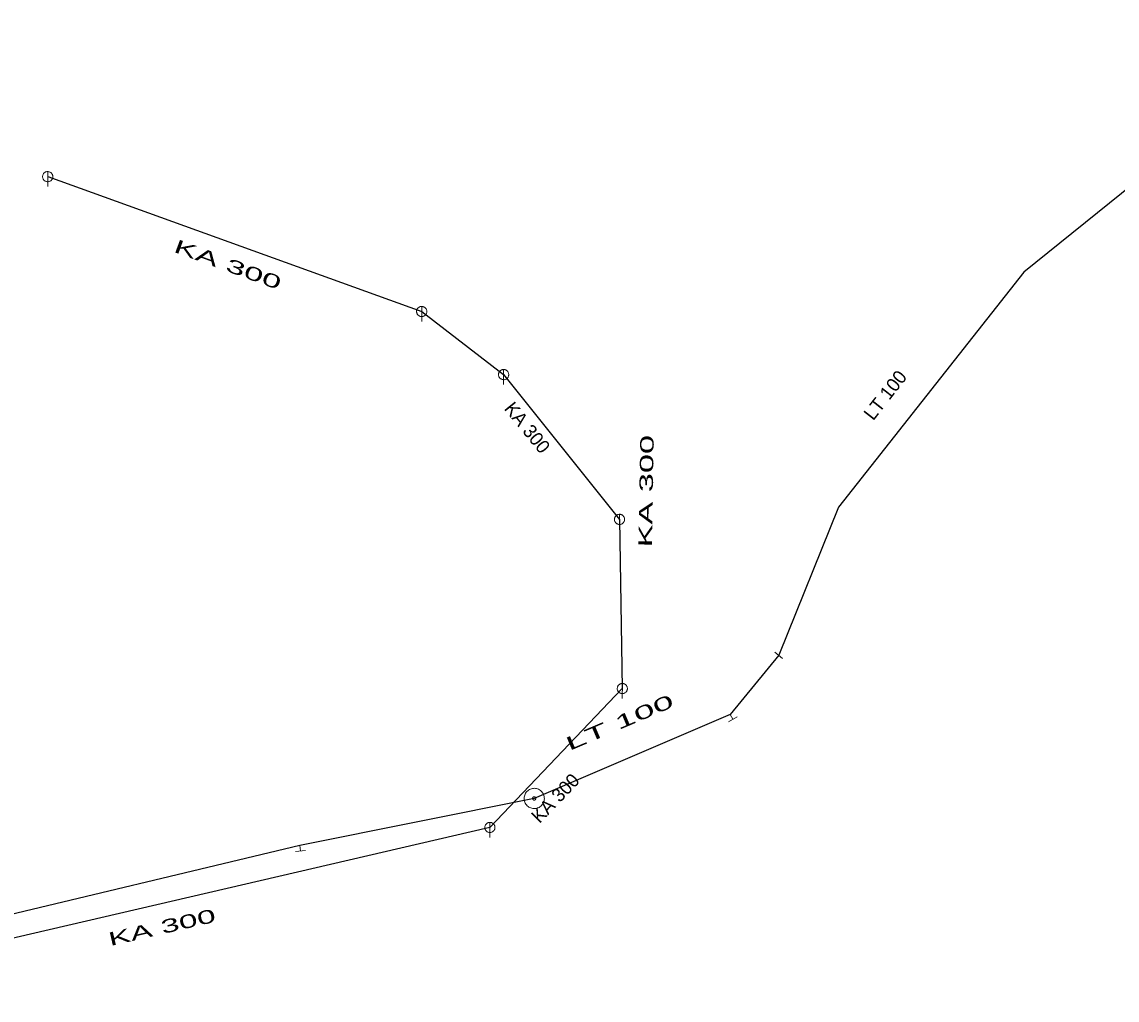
# Model space of a CAD drawing. Extents: x -687515 to -686506, y -974029 to -973461.
# Drawn here: x -687015 to -686960.9, y -973763.4 to -973715 of the extents above; entities that cross this region are included whole.
import ezdxf
from ezdxf.enums import TextEntityAlignment as Align

# ---------------------------------------------------------------- set-up
doc = ezdxf.new("R2010")
doc.units = 0
doc.header["$LTSCALE"] = 0.27
for name, color, linetype, lineweight in [('1', 7, 'Continuous', 13), ('14', 7, 'Continuous', 25), ('17', 7, 'Continuous', 25), ('22', 7, 'Continuous', 13), ('34', 7, 'Continuous', 13), ('47', 7, 'Continuous', 13)]:
    doc.layers.add(name, color=color, linetype=linetype, lineweight=lineweight)

msp = doc.modelspace()

# ---------------------------------------------------------------- linework, layer by layer
at = {"layer": '14'}
for p, q in [((-687013.763, -973722.649), (-686995.27, -973729.32)), ((-686995.27, -973729.32), (-686991.219, -973732.44)), ((-686985.35, -973747.969), (-686991.899, -973754.84)), ((-686991.899, -973754.84), (-687024.84, -973762.48))]:
    msp.add_line(p, q, dxfattribs=at)
at = {"layer": '14', "lineweight": 13}
for p, q in [((-686980.017, -973749.259), (-686979.889, -973749.489)), ((-687001.294, -973755.738), (-687001.27, -973756))]:
    msp.add_line(p, q, dxfattribs=at)
at = {"layer": '14'}
msp.add_lwpolyline([(-686991.219, -973732.44), (-686985.489, -973739.6), (-686985.35, -973747.969)], dxfattribs=at)
at = {"layer": '17'}
for points in [[(-686948.922, -973714.994), (-686954.652, -973718.63), (-686965.5, -973727.379), (-686974.664, -973738.999), (-686977.613, -973746.323)], [(-686977.613, -973746.323), (-686980.017, -973749.259), (-686989.707, -973753.404)], [(-686989.707, -973753.404), (-687001.294, -973755.738), (-687033.846, -973763.506), (-687042.734, -973766.009), (-687045.081, -973767.522), (-687056.296, -973773.572), (-687070.532, -973788), (-687086.733, -973803.447)]]:
    msp.add_lwpolyline(points, dxfattribs=at)
at = {"layer": '22'}
for p, q in [((-687013.762, -973722.397), (-687013.763, -973723.141)), ((-686995.269, -973729.068), (-686995.27, -973729.811)), ((-686991.218, -973732.188), (-686991.219, -973732.931)), ((-686985.488, -973739.348), (-686985.489, -973740.092)), ((-686985.349, -973747.717), (-686985.35, -973748.461)), ((-686991.898, -973754.588), (-686991.899, -973755.331))]:
    msp.add_line(p, q, dxfattribs=at)
for points in [[(-687013.511, -973722.649), (-687013.512, -973722.623), (-687013.516, -973722.597), (-687013.522, -973722.571), (-687013.532, -973722.547), (-687013.544, -973722.523), (-687013.558, -973722.501), (-687013.575, -973722.48), (-687013.593, -973722.462), (-687013.614, -973722.445), (-687013.636, -973722.431), (-687013.66, -973722.419), (-687013.684, -973722.409), (-687013.71, -973722.403), (-687013.736, -973722.399), (-687013.762, -973722.397), (-687013.788, -973722.398), (-687013.814, -973722.402), (-687013.84, -973722.408), (-687013.865, -973722.418), (-687013.888, -973722.43), (-687013.91, -973722.444), (-687013.931, -973722.461), (-687013.949, -973722.479), (-687013.966, -973722.5), (-687013.98, -973722.522), (-687013.992, -973722.546), (-687014.002, -973722.57), (-687014.009, -973722.596), (-687014.013, -973722.622), (-687014.015, -973722.648), (-687014.014, -973722.674), (-687014.01, -973722.7), (-687014.003, -973722.726), (-687013.993, -973722.751), (-687013.981, -973722.774), (-687013.967, -973722.796), (-687013.95, -973722.817), (-687013.932, -973722.835), (-687013.911, -973722.852), (-687013.889, -973722.866), (-687013.866, -973722.878), (-687013.841, -973722.888), (-687013.815, -973722.895), (-687013.789, -973722.899), (-687013.763, -973722.901), (-687013.737, -973722.9), (-687013.711, -973722.896), (-687013.685, -973722.889), (-687013.661, -973722.879), (-687013.637, -973722.867), (-687013.615, -973722.853), (-687013.594, -973722.836), (-687013.576, -973722.818), (-687013.559, -973722.797), (-687013.545, -973722.775), (-687013.533, -973722.752), (-687013.523, -973722.727), (-687013.517, -973722.701), (-687013.513, -973722.675)], [(-686995.018, -973729.32), (-686995.019, -973729.294), (-686995.023, -973729.268), (-686995.029, -973729.242), (-686995.039, -973729.218), (-686995.051, -973729.194), (-686995.065, -973729.172), (-686995.082, -973729.151), (-686995.1, -973729.133), (-686995.121, -973729.116), (-686995.143, -973729.102), (-686995.167, -973729.09), (-686995.191, -973729.08), (-686995.217, -973729.074), (-686995.243, -973729.07), (-686995.269, -973729.068), (-686995.295, -973729.069), (-686995.321, -973729.073), (-686995.347, -973729.079), (-686995.372, -973729.089), (-686995.395, -973729.101), (-686995.417, -973729.115), (-686995.438, -973729.132), (-686995.456, -973729.15), (-686995.473, -973729.171), (-686995.487, -973729.193), (-686995.499, -973729.217), (-686995.509, -973729.241), (-686995.516, -973729.267), (-686995.52, -973729.293), (-686995.522, -973729.319), (-686995.521, -973729.345), (-686995.517, -973729.371), (-686995.51, -973729.397), (-686995.5, -973729.422), (-686995.488, -973729.445), (-686995.474, -973729.467), (-686995.457, -973729.488), (-686995.439, -973729.506), (-686995.418, -973729.523), (-686995.396, -973729.537), (-686995.373, -973729.549), (-686995.348, -973729.559), (-686995.322, -973729.566), (-686995.296, -973729.57), (-686995.27, -973729.571), (-686995.244, -973729.571), (-686995.218, -973729.567), (-686995.192, -973729.56), (-686995.168, -973729.55), (-686995.144, -973729.538), (-686995.122, -973729.524), (-686995.101, -973729.507), (-686995.083, -973729.489), (-686995.066, -973729.468), (-686995.052, -973729.446), (-686995.04, -973729.423), (-686995.03, -973729.398), (-686995.024, -973729.372), (-686995.02, -973729.346)], [(-686990.967, -973732.44), (-686990.968, -973732.414), (-686990.972, -973732.388), (-686990.978, -973732.362), (-686990.988, -973732.338), (-686991, -973732.314), (-686991.014, -973732.292), (-686991.031, -973732.271), (-686991.049, -973732.253), (-686991.07, -973732.236), (-686991.092, -973732.222), (-686991.116, -973732.21), (-686991.14, -973732.2), (-686991.166, -973732.194), (-686991.192, -973732.19), (-686991.218, -973732.188), (-686991.244, -973732.189), (-686991.27, -973732.193), (-686991.296, -973732.199), (-686991.321, -973732.209), (-686991.344, -973732.221), (-686991.366, -973732.235), (-686991.387, -973732.252), (-686991.405, -973732.27), (-686991.422, -973732.291), (-686991.436, -973732.313), (-686991.448, -973732.337), (-686991.458, -973732.361), (-686991.465, -973732.387), (-686991.469, -973732.413), (-686991.471, -973732.439), (-686991.47, -973732.465), (-686991.466, -973732.491), (-686991.459, -973732.517), (-686991.449, -973732.542), (-686991.437, -973732.565), (-686991.423, -973732.587), (-686991.406, -973732.608), (-686991.388, -973732.626), (-686991.367, -973732.643), (-686991.345, -973732.657), (-686991.322, -973732.669), (-686991.297, -973732.679), (-686991.271, -973732.686), (-686991.245, -973732.69), (-686991.219, -973732.691), (-686991.193, -973732.691), (-686991.167, -973732.687), (-686991.141, -973732.68), (-686991.117, -973732.67), (-686991.093, -973732.658), (-686991.071, -973732.644), (-686991.05, -973732.627), (-686991.032, -973732.609), (-686991.015, -973732.588), (-686991.001, -973732.566), (-686990.989, -973732.543), (-686990.979, -973732.518), (-686990.973, -973732.492), (-686990.969, -973732.466)], [(-686985.237, -973739.6), (-686985.238, -973739.574), (-686985.242, -973739.548), (-686985.248, -973739.522), (-686985.258, -973739.498), (-686985.27, -973739.474), (-686985.284, -973739.452), (-686985.301, -973739.431), (-686985.319, -973739.413), (-686985.34, -973739.396), (-686985.362, -973739.382), (-686985.386, -973739.37), (-686985.41, -973739.36), (-686985.436, -973739.354), (-686985.462, -973739.35), (-686985.488, -973739.348), (-686985.514, -973739.349), (-686985.54, -973739.353), (-686985.566, -973739.359), (-686985.591, -973739.369), (-686985.614, -973739.381), (-686985.636, -973739.395), (-686985.657, -973739.412), (-686985.675, -973739.43), (-686985.692, -973739.451), (-686985.706, -973739.473), (-686985.718, -973739.497), (-686985.728, -973739.521), (-686985.735, -973739.547), (-686985.739, -973739.573), (-686985.74, -973739.599), (-686985.74, -973739.625), (-686985.736, -973739.651), (-686985.729, -973739.677), (-686985.719, -973739.702), (-686985.707, -973739.725), (-686985.693, -973739.747), (-686985.676, -973739.768), (-686985.658, -973739.786), (-686985.637, -973739.803), (-686985.615, -973739.817), (-686985.592, -973739.829), (-686985.567, -973739.839), (-686985.541, -973739.846), (-686985.515, -973739.85), (-686985.489, -973739.852), (-686985.463, -973739.851), (-686985.437, -973739.847), (-686985.411, -973739.84), (-686985.387, -973739.83), (-686985.363, -973739.818), (-686985.341, -973739.804), (-686985.32, -973739.787), (-686985.302, -973739.769), (-686985.285, -973739.748), (-686985.271, -973739.726), (-686985.259, -973739.703), (-686985.249, -973739.678), (-686985.243, -973739.652), (-686985.239, -973739.626)], [(-686985.098, -973747.969), (-686985.099, -973747.943), (-686985.103, -973747.917), (-686985.109, -973747.891), (-686985.119, -973747.867), (-686985.131, -973747.843), (-686985.145, -973747.821), (-686985.162, -973747.8), (-686985.18, -973747.782), (-686985.201, -973747.765), (-686985.223, -973747.751), (-686985.247, -973747.739), (-686985.271, -973747.729), (-686985.297, -973747.723), (-686985.323, -973747.719), (-686985.349, -973747.717), (-686985.375, -973747.718), (-686985.401, -973747.722), (-686985.427, -973747.728), (-686985.452, -973747.738), (-686985.475, -973747.75), (-686985.497, -973747.764), (-686985.518, -973747.781), (-686985.536, -973747.799), (-686985.553, -973747.82), (-686985.567, -973747.842), (-686985.579, -973747.866), (-686985.589, -973747.89), (-686985.596, -973747.916), (-686985.6, -973747.942), (-686985.602, -973747.968), (-686985.601, -973747.994), (-686985.597, -973748.02), (-686985.59, -973748.046), (-686985.58, -973748.071), (-686985.568, -973748.094), (-686985.554, -973748.116), (-686985.537, -973748.137), (-686985.519, -973748.155), (-686985.498, -973748.172), (-686985.476, -973748.186), (-686985.453, -973748.198), (-686985.428, -973748.208), (-686985.402, -973748.215), (-686985.376, -973748.219), (-686985.35, -973748.221), (-686985.324, -973748.22), (-686985.298, -973748.216), (-686985.272, -973748.209), (-686985.248, -973748.199), (-686985.224, -973748.187), (-686985.202, -973748.173), (-686985.181, -973748.156), (-686985.163, -973748.138), (-686985.146, -973748.117), (-686985.132, -973748.095), (-686985.12, -973748.072), (-686985.11, -973748.047), (-686985.104, -973748.021), (-686985.1, -973747.995)], [(-686991.647, -973754.84), (-686991.648, -973754.814), (-686991.652, -973754.788), (-686991.658, -973754.762), (-686991.668, -973754.738), (-686991.68, -973754.714), (-686991.694, -973754.692), (-686991.711, -973754.671), (-686991.729, -973754.653), (-686991.75, -973754.636), (-686991.772, -973754.622), (-686991.796, -973754.61), (-686991.82, -973754.6), (-686991.846, -973754.594), (-686991.872, -973754.59), (-686991.898, -973754.588), (-686991.924, -973754.589), (-686991.95, -973754.593), (-686991.976, -973754.599), (-686992.001, -973754.609), (-686992.024, -973754.621), (-686992.046, -973754.635), (-686992.067, -973754.652), (-686992.085, -973754.67), (-686992.102, -973754.691), (-686992.116, -973754.713), (-686992.128, -973754.737), (-686992.138, -973754.761), (-686992.145, -973754.787), (-686992.149, -973754.813), (-686992.151, -973754.839), (-686992.15, -973754.865), (-686992.146, -973754.891), (-686992.139, -973754.917), (-686992.129, -973754.942), (-686992.117, -973754.965), (-686992.103, -973754.987), (-686992.086, -973755.008), (-686992.068, -973755.026), (-686992.047, -973755.043), (-686992.025, -973755.057), (-686992.002, -973755.069), (-686991.977, -973755.079), (-686991.951, -973755.086), (-686991.925, -973755.09), (-686991.899, -973755.092), (-686991.873, -973755.091), (-686991.847, -973755.087), (-686991.821, -973755.08), (-686991.797, -973755.07), (-686991.773, -973755.058), (-686991.751, -973755.044), (-686991.73, -973755.027), (-686991.712, -973755.009), (-686991.695, -973754.988), (-686991.681, -973754.966), (-686991.669, -973754.943), (-686991.659, -973754.918), (-686991.653, -973754.892), (-686991.649, -973754.866)]]:
    msp.add_lwpolyline(points, close=True, dxfattribs=at)
at = {"layer": '34'}
for p, q in [((-686977.424, -973746.483), (-686977.801, -973746.162)), ((-686980.106, -973749.608), (-686979.671, -973749.369)), ((-687001.516, -973756.022), (-687001.023, -973755.977))]:
    msp.add_line(p, q, dxfattribs=at)
at = {"layer": '47'}
for points in [[(-686989.4, -973753.008), (-686989.443, -973752.979), (-686989.489, -973752.953), (-686989.538, -973752.934), (-686989.587, -973752.918), (-686989.639, -973752.908), (-686989.692, -973752.904), (-686989.744, -973752.906), (-686989.795, -973752.912), (-686989.846, -973752.924), (-686989.896, -973752.941), (-686989.944, -973752.963), (-686989.988, -973752.991), (-686990.03, -973753.022), (-686990.068, -973753.058), (-686990.102, -973753.097), (-686990.131, -973753.14), (-686990.157, -973753.186), (-686990.177, -973753.235), (-686990.192, -973753.284), (-686990.202, -973753.336), (-686990.206, -973753.389), (-686990.205, -973753.441), (-686990.198, -973753.493), (-686990.187, -973753.544), (-686990.169, -973753.593), (-686990.147, -973753.641), (-686990.12, -973753.686), (-686990.088, -973753.727), (-686990.052, -973753.765), (-686990.013, -973753.799), (-686989.97, -973753.828), (-686989.924, -973753.854), (-686989.875, -973753.875), (-686989.826, -973753.889), (-686989.774, -973753.899), (-686989.722, -973753.904), (-686989.669, -973753.903), (-686989.617, -973753.896), (-686989.566, -973753.884), (-686989.517, -973753.866), (-686989.469, -973753.844), (-686989.425, -973753.817), (-686989.383, -973753.785), (-686989.345, -973753.749), (-686989.311, -973753.71), (-686989.282, -973753.667), (-686989.256, -973753.621), (-686989.236, -973753.573), (-686989.221, -973753.523), (-686989.211, -973753.471), (-686989.206, -973753.419), (-686989.208, -973753.367), (-686989.215, -973753.315), (-686989.227, -973753.264), (-686989.244, -973753.214), (-686989.266, -973753.166), (-686989.293, -973753.123), (-686989.325, -973753.08), (-686989.361, -973753.042)], [(-686989.656, -973753.339), (-686989.663, -973753.333), (-686989.671, -973753.33), (-686989.679, -973753.327), (-686989.687, -973753.324), (-686989.695, -973753.322), (-686989.704, -973753.322), (-686989.713, -973753.322), (-686989.721, -973753.323), (-686989.729, -973753.325), (-686989.738, -973753.328), (-686989.746, -973753.332), (-686989.753, -973753.336), (-686989.759, -973753.341), (-686989.766, -973753.346), (-686989.771, -973753.353), (-686989.777, -973753.36), (-686989.78, -973753.368), (-686989.783, -973753.376), (-686989.786, -973753.384), (-686989.788, -973753.392), (-686989.788, -973753.401), (-686989.788, -973753.41), (-686989.787, -973753.418), (-686989.785, -973753.427), (-686989.782, -973753.435), (-686989.778, -973753.443), (-686989.774, -973753.45), (-686989.769, -973753.456), (-686989.764, -973753.463), (-686989.757, -973753.468), (-686989.75, -973753.474), (-686989.742, -973753.477), (-686989.734, -973753.48), (-686989.726, -973753.483), (-686989.718, -973753.485), (-686989.71, -973753.486), (-686989.7, -973753.485), (-686989.692, -973753.484), (-686989.683, -973753.482), (-686989.675, -973753.479), (-686989.667, -973753.475), (-686989.66, -973753.471), (-686989.654, -973753.466), (-686989.647, -973753.461), (-686989.642, -973753.454), (-686989.636, -973753.447), (-686989.633, -973753.439), (-686989.63, -973753.431), (-686989.627, -973753.423), (-686989.625, -973753.415), (-686989.624, -973753.407), (-686989.625, -973753.397), (-686989.626, -973753.389), (-686989.628, -973753.381), (-686989.631, -973753.372), (-686989.635, -973753.364), (-686989.639, -973753.357), (-686989.644, -973753.351), (-686989.649, -973753.344)]]:
    msp.add_lwpolyline(points, close=True, dxfattribs=at)

# ---------------------------------------------------------------- texts
at = {"layer": '1'}
for s, rotation, width, p in [('KA 300', 340, 1.9, (-687004.971, -973727.306)), ('KA 300', 89, 1.9, (-686983.841, -973738.211)), ('LT 100', 23, 2.05, (-686985.355, -973749.949)), ('KA 300', 13, 1.85, (-687008.038, -973760.102))]:
    msp.add_text(s, height=0.6667, rotation=rotation, dxfattribs=dict(at, width=width)).set_placement(p, align=Align.CENTER)
for s, rotation, p in [('LT 100', 52, (-686972.089, -973733.659)), ('KA 300', 309, (-686990.306, -973735.27)), ('KA 300', 46, (-686988.424, -973753.619))]:
    msp.add_text(s, height=0.6667, rotation=rotation, dxfattribs=at).set_placement(p, align=Align.CENTER)

doc.saveas('drawing.dxf')
